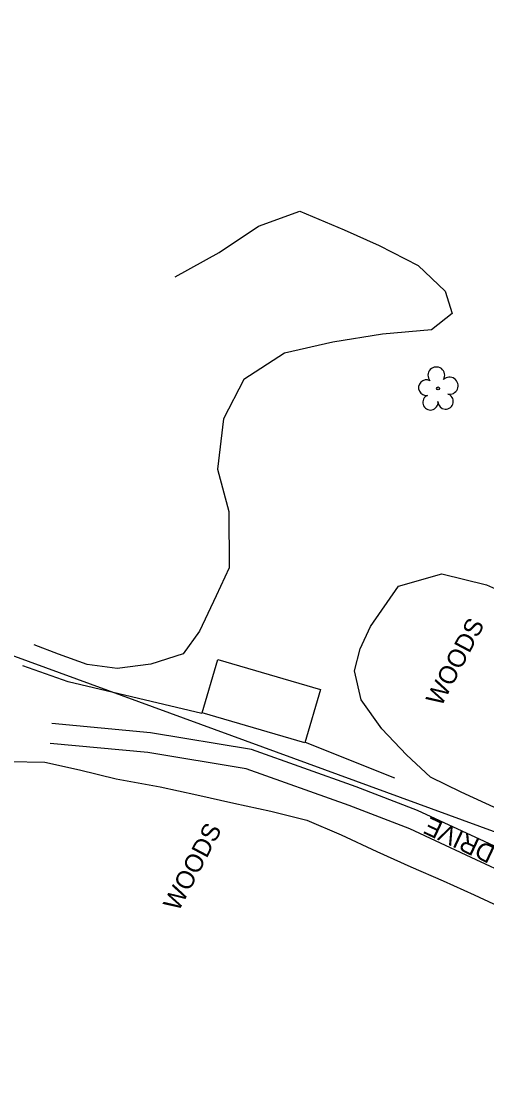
# Model space of a CAD drawing. Extents: x 1149843 to 1151668, y 621784 to 624721.
# Drawn here: x 1150381.1 to 1150484.2, y 623034.1 to 623269.9 of the extents above; entities that cross this region are included whole.
import ezdxf

# ---------------------------------------------------------------- set-up
doc = ezdxf.new("R2010")
doc.units = 0
for name, color, linetype in [('Exist Building', 7, 'Continuous'), ('Exist Other Culture Fence Line', 7, 'Continuous'), ('Exist Property Line', 7, 'Continuous'), ('Exist Roads Soil', 7, 'Continuous'), ('Exist Roads Soil Text', 7, 'Continuous'), ('Exist Vegetation Tree CELL', 7, 'Continuous'), ('Exist Vegetation Woods Line', 7, 'Continuous'), ('Exist Vegetation Woods Line Text', 7, 'Continuous')]:
    doc.layers.add(name, color=color, linetype=linetype)

msp = doc.modelspace()

# ---------------------------------------------------------------- linework, layer by layer
at = {"layer": 'Exist Building'}
msp.add_lwpolyline([(1150424.65, 623128.45), (1150447.39, 623121.77), (1150443.92, 623109.95), (1150421.18, 623116.63)], close=True, dxfattribs=at)
at = {"layer": 'Exist Other Culture Fence Line'}
for points in [[(1150421.08, 623116.44), (1150391.48, 623123.45), (1150381.45, 623127.04)], [(1150444.01, 623110.13), (1150463.79, 623102.15)]]:
    msp.add_lwpolyline(points, dxfattribs=at)
at = {"layer": 'Exist Property Line'}
msp.add_line((1150597.46, 623049.4), (1149994.47, 623269.92), dxfattribs=at)
at = {"layer": 'Exist Roads Soil'}
for points in [[(1150578.59, 623038.29), (1150569.46, 623041.75), (1150559.03, 623046.11), (1150546.96, 623051.98), (1150535.92, 623058.21), (1150529.56, 623062.61), (1150520.54, 623068.24), (1150508.02, 623076.52), (1150498.41, 623081.18), (1150483.76, 623088.05), (1150468.89, 623094.94), (1150455.3, 623100.19), (1150432.08, 623108.49), (1150409.74, 623112.19), (1150387.88, 623114.22)], [(1150577.02, 623034.15), (1150567.82, 623037.63), (1150557.2, 623042.07), (1150544.9, 623048.06), (1150533.56, 623054.45), (1150527.12, 623058.91), (1150518.15, 623064.51), (1150505.82, 623072.66), (1150496.51, 623077.18), (1150481.89, 623084.03), (1150467.15, 623090.86), (1150453.75, 623096.03), (1150430.96, 623104.19), (1150409.17, 623107.79), (1150387.47, 623109.81)]]:
    msp.add_lwpolyline(points, dxfattribs=at)
at = {"layer": 'Exist Vegetation Tree CELL'}
msp.add_line((1150473.44, 623188.53), (1150473.44, 623188.53), dxfattribs=at)
msp.add_circle((1150473.44, 623188.53), 0.326, dxfattribs=at)
for centre, radius, start, end in [((1150473.06, 623191.41), 1.86, 330.1651, 219.7134), ((1150470.84, 623188.69), 1.73, 62.6636, 279.3457), ((1150475.99, 623189.12), 1.9, 257.1011, 134.1999), ((1150471.74, 623185.41), 1.69, 111.5671, 6.231), ((1150475.12, 623185.63), 1.7, 181.2822, 74.56)]:
    msp.add_arc(centre, radius, start, end, dxfattribs=at)
at = {"layer": 'Exist Vegetation Woods Line'}
for points in [[(1150415.18, 623213.24), (1150424.96, 623218.62), (1150433.63, 623224.49), (1150442.85, 623227.84), (1150452.62, 623223.69), (1150460.39, 623220.21), (1150469.01, 623215.8), (1150475.01, 623210.07), (1150476.55, 623205.11), (1150472.01, 623201.54), (1150461.13, 623200.55), (1150450.13, 623198.79), (1150439.42, 623196.31), (1150430.42, 623190.5), (1150425.91, 623181.8), (1150424.6, 623170.59), (1150427.12, 623161.24), (1150427.15, 623148.72)], [(1150427.15, 623148.72), (1150424.29, 623142.55), (1150420.62, 623134.67), (1150416.98, 623129.68), (1150409.81, 623127.4), (1150402.38, 623126.43), (1150395.71, 623127.28), (1150389.33, 623129.6), (1150383.99, 623131.64)], [(1150458.5, 623135.77), (1150464.64, 623144.66), (1150474.26, 623147.39), (1150484.15, 623145), (1150493.46, 623140.82), (1150503.63, 623136.28), (1150514.31, 623133.78), (1150525.71, 623131.13), (1150535.7, 623128.58), (1150544.35, 623130.98), (1150549.53, 623135.1), (1150556.34, 623138.07), (1150565.64, 623136.78), (1150575.38, 623131.99), (1150582.83, 623121.52), (1150586.77, 623109.08), (1150590, 623098), (1150596.24, 623071.78)], [(1150596.24, 623071.78), (1150598.93, 623062.97), (1150598.87, 623055.98), (1150596.17, 623050.05), (1150591.08, 623047.47), (1150583.74, 623047.84), (1150576.41, 623051.68), (1150567.51, 623055.94), (1150542.57, 623067.99), (1150523.8, 623077.1), (1150503.81, 623087.31), (1150486.74, 623095.22), (1150478.55, 623099.01), (1150471.74, 623102.33), (1150466.46, 623107.32), (1150460.96, 623113.05), (1150456.38, 623119.48), (1150454.91, 623125.88), (1150456.2, 623130.76), (1150458.5, 623135.77)], [(1150378.45, 623105.82), (1150386.31, 623105.63), (1150394.04, 623103.96), (1150402.09, 623101.94), (1150411.87, 623100.2), (1150420.01, 623098.4), (1150428.2, 623096.56), (1150436.38, 623094.76), (1150444.38, 623092.79), (1150451.98, 623089.52), (1150459.85, 623085.88), (1150467.38, 623082.46), (1150474.6, 623079.35), (1150481.47, 623076.23), (1150488.93, 623072.78)]]:
    msp.add_lwpolyline(points, dxfattribs=at)

# ---------------------------------------------------------------- texts
at = {"layer": 'Exist Roads Soil Text'}
msp.add_text('& CONC. DRIVE', height=4, rotation=154.7929, dxfattribs=at).set_placement((1150507.9, 623076.59))
at = {"layer": 'Exist Vegetation Woods Line Text'}
for p in [(1150474.11, 623117.8), (1150415.91, 623072.36)]:
    msp.add_text('WOODS', height=4, rotation=62.1899, dxfattribs=at).set_placement(p)

doc.saveas('drawing.dxf')
